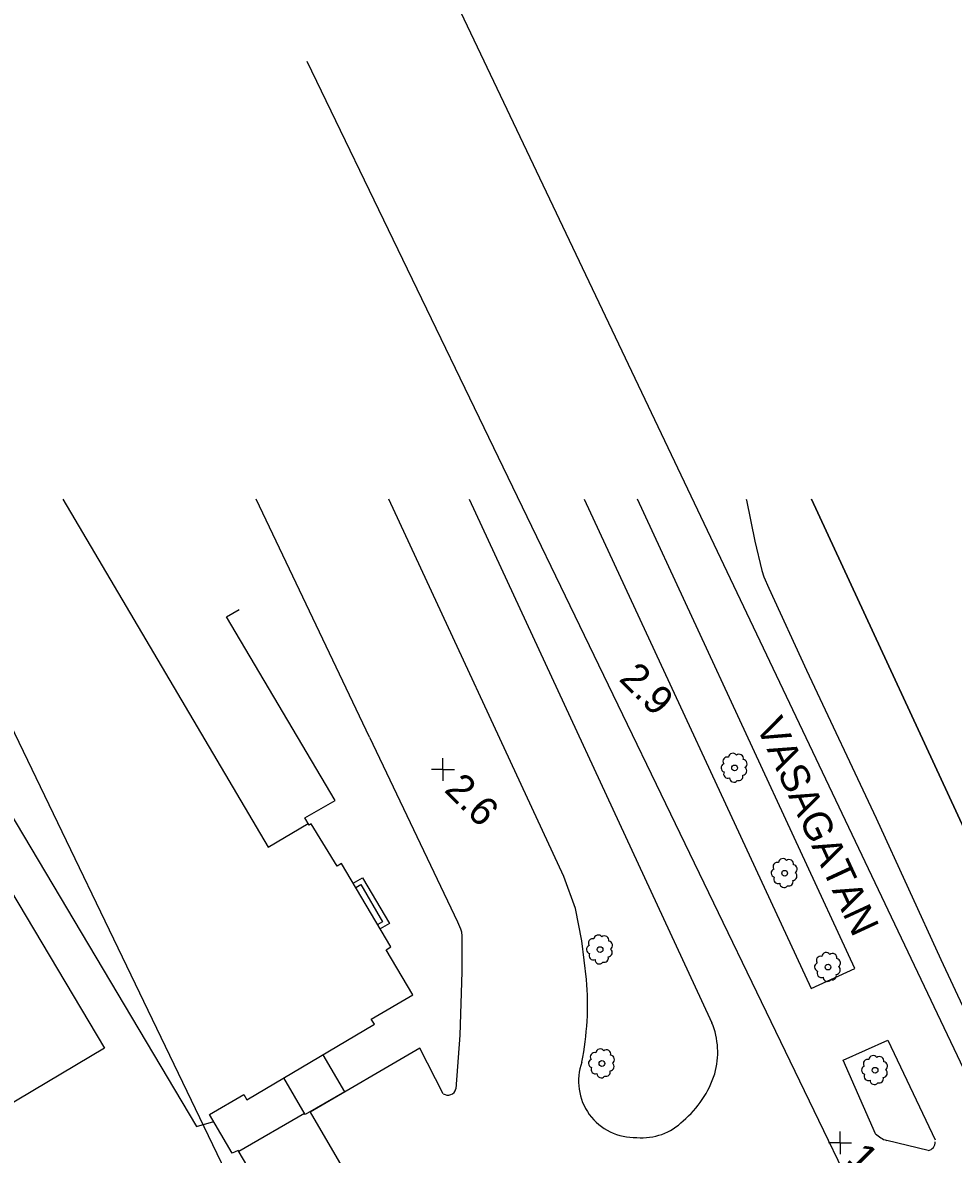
# Model space of a CAD drawing. Extents: x 1596643 to 1597288, y 13057194 to 13057957.
# Drawn here: x 1596883 to 1596964.2, y 13057602 to 13057700.7 of the extents above; entities that cross this region are included whole.
import ezdxf

# ---------------------------------------------------------------- set-up
doc = ezdxf.new("R2010")
doc.units = 0
for name, color, linetype in [('BAS byggnad anläggning L', 7, 'Continuous'), ('BAS fastighetsgräns samfällighet L', 7, 'Continuous'), ('BAS Level 16', 7, 'Continuous'), ('BAS Level 19', 7, 'Continuous'), ('BAS Level 37', 7, 'Continuous'), ('BAS lövträd P', 7, 'Continuous'), ('BAS markytetext T', 7, 'Continuous'), ('BAS trappa L', 7, 'Continuous'), ('BAS väg T', 7, 'Continuous'), ('BAS vägbanekant L', 7, 'Continuous')]:
    doc.layers.add(name, color=color, linetype=linetype)

msp = doc.modelspace()

# ---------------------------------------------------------------- linework, layer by layer
at = {"layer": 'BAS byggnad anläggning L'}
for points in [[(1596831.406, 13057716.961), (1596833.516, 13057713.232), (1596898.19, 13057604.41), (1596899.706, 13057604.86)], [(1596834.085, 13057712.226), (1596832.695, 13057711.294), (1596834.411, 13057708.471), (1596832.821, 13057707.631), (1596890.171, 13057611.249), (1596868.668, 13057598.445)], [(1596886.54, 13057659.15), (1596904.445, 13057628.802), (1596907.94, 13057630.864)], [(1596951.85, 13057659.15), (1596967.176, 13057626.043), (1596968.373, 13057623.457)], [(1596908.21, 13057630.819), (1596908.034, 13057630.704), (1596907.658, 13057631.341), (1596910.303, 13057632.867), (1596900.808, 13057648.889), (1596901.929, 13057649.518)], [(1596911.31, 13057586.299), (1596901.852, 13057602.339), (1596901.33, 13057602.091), (1596899.353, 13057605.461), (1596902.324, 13057607.201), (1596902.603, 13057606.75), (1596913.738, 13057613.344), (1596913.45, 13057613.785), (1596917.076, 13057615.913), (1596914.761, 13057619.836), (1596915.171, 13057620.084), (1596910.858, 13057627.367), (1596910.489, 13057627.128), (1596908.21, 13057630.819)], [(1596909.211, 13057610.663), (1596911.108, 13057607.434), (1596907.683, 13057605.454), (1596905.829, 13057608.661)]]:
    msp.add_lwpolyline(points, dxfattribs=at)
at = {"layer": 'BAS fastighetsgräns samfällighet L'}
for points in [[(1596920.393, 13057703.458), (1596969.695, 13057599.79)], [(1596957.924, 13057593.7), (1596907.849, 13057697.344)], [(1596913.913, 13057573.162), (1596863.532, 13057677.717)]]:
    msp.add_lwpolyline(points, dxfattribs=at)
at = {"layer": 'BAS Level 16'}
for p, q in [((1596919.698, 13057635.566), (1596919.698, 13057636.566)), ((1596919.698, 13057635.566), (1596919.698, 13057636.566)), ((1596919.698, 13057635.566), (1596918.698, 13057635.566)), ((1596919.698, 13057635.566), (1596918.698, 13057635.566)), ((1596919.698, 13057635.566), (1596920.698, 13057635.566)), ((1596919.698, 13057635.566), (1596919.698, 13057634.566)), ((1596919.698, 13057635.566), (1596920.698, 13057635.566)), ((1596919.698, 13057635.566), (1596919.698, 13057634.566)), ((1596954.343, 13057602.996), (1596954.343, 13057603.996)), ((1596954.343, 13057602.996), (1596954.343, 13057603.996)), ((1596954.343, 13057602.996), (1596953.343, 13057602.996)), ((1596954.343, 13057602.996), (1596953.343, 13057602.996)), ((1596954.343, 13057602.996), (1596955.343, 13057602.996)), ((1596954.343, 13057602.996), (1596954.343, 13057601.996)), ((1596954.343, 13057602.996), (1596955.343, 13057602.996)), ((1596954.343, 13057602.996), (1596954.343, 13057601.996))]:
    msp.add_line(p, q, dxfattribs=at)
at = {"layer": 'BAS Level 19'}
msp.add_lwpolyline([(1596907.633, 13057605.541), (1596901.893, 13057602.234)], dxfattribs=at)
at = {"layer": 'BAS Level 37'}
msp.add_lwpolyline([(1596967.176, 13057626.043), (1596951.85, 13057659.15)], dxfattribs=at)
at = {"layer": 'BAS lövträd P'}
for p, q in [((1596945.144, 13057635.703), (1596945.144, 13057635.703)), ((1596945.144, 13057635.703), (1596945.144, 13057635.703)), ((1596949.516, 13057626.517), (1596949.516, 13057626.517)), ((1596949.516, 13057626.517), (1596949.516, 13057626.517)), ((1596933.407, 13057619.852), (1596933.407, 13057619.852)), ((1596933.407, 13057619.852), (1596933.407, 13057619.852)), ((1596953.295, 13057618.326), (1596953.295, 13057618.326)), ((1596953.295, 13057618.326), (1596953.295, 13057618.326)), ((1596933.572, 13057609.914), (1596933.572, 13057609.914)), ((1596933.572, 13057609.914), (1596933.572, 13057609.914)), ((1596957.399, 13057609.329), (1596957.399, 13057609.329)), ((1596957.399, 13057609.329), (1596957.399, 13057609.329))]:
    msp.add_line(p, q, dxfattribs=at)
for centre in [(1596945.144, 13057635.703), (1596945.144, 13057635.703), (1596949.516, 13057626.517), (1596949.516, 13057626.517), (1596933.407, 13057619.852), (1596933.407, 13057619.852), (1596953.295, 13057618.326), (1596953.295, 13057618.326), (1596933.572, 13057609.914), (1596933.572, 13057609.914), (1596957.399, 13057609.329), (1596957.399, 13057609.329)]:
    msp.add_circle(centre, 0.25, dxfattribs=at)
for centre, start, end in [((1596944.34, 13057635.715), 112.50794, 253.98582), ((1596944.34, 13057635.715), 112.50794, 253.98582), ((1596944.505, 13057636.275), 73.07604, 214.55393), ((1596944.505, 13057636.275), 73.07604, 214.55393), ((1596944.988, 13057636.601), 33.64415, 175.12203), ((1596944.988, 13057636.601), 33.64415, 175.12203), ((1596945.538, 13057636.518), 347.91483, 129.39271), ((1596945.538, 13057636.518), 347.91483, 129.39271), ((1596945.858, 13057636.068), 301.35804, 82.83592), ((1596945.858, 13057636.068), 301.35804, 82.83592), ((1596944.565, 13057635.175), 151.38275, 292.86063), ((1596944.565, 13057635.175), 151.38275, 292.86063), ((1596945.498, 13057634.967), 253.13635, 15.42798), ((1596945.498, 13057634.967), 253.13635, 15.42798), ((1596945.837, 13057635.441), 273.337, 54.81488), ((1596945.837, 13057635.441), 273.337, 54.81488), ((1596945.086, 13057634.828), 179.81921, 321.29709), ((1596945.086, 13057634.828), 179.81921, 321.29709), ((1596948.877, 13057627.089), 73.07604, 214.55393), ((1596948.877, 13057627.089), 73.07604, 214.55393), ((1596949.36, 13057627.415), 33.64415, 175.12203), ((1596949.36, 13057627.415), 33.64415, 175.12203), ((1596949.91, 13057627.332), 347.91483, 129.39271), ((1596949.91, 13057627.332), 347.91483, 129.39271), ((1596950.23, 13057626.882), 301.35804, 82.83592), ((1596950.23, 13057626.882), 301.35804, 82.83592), ((1596948.712, 13057626.529), 112.50794, 253.98582), ((1596948.712, 13057626.529), 112.50794, 253.98582), ((1596948.937, 13057625.989), 151.38275, 292.86063), ((1596948.937, 13057625.989), 151.38275, 292.86063), ((1596950.209, 13057626.255), 273.337, 54.81488), ((1596950.209, 13057626.255), 273.337, 54.81488), ((1596949.458, 13057625.642), 179.81921, 321.29709), ((1596949.458, 13057625.642), 179.81921, 321.29709), ((1596949.87, 13057625.781), 253.13635, 15.42798), ((1596949.87, 13057625.781), 253.13635, 15.42798), ((1596932.603, 13057619.864), 112.50794, 253.98582), ((1596932.603, 13057619.864), 112.50794, 253.98582), ((1596932.768, 13057620.424), 73.07604, 214.55393), ((1596932.768, 13057620.424), 73.07604, 214.55393), ((1596933.251, 13057620.75), 33.64415, 175.12203), ((1596933.251, 13057620.75), 33.64415, 175.12203), ((1596933.801, 13057620.667), 347.91483, 129.39271), ((1596933.801, 13057620.667), 347.91483, 129.39271), ((1596934.121, 13057620.217), 301.35804, 82.83592), ((1596934.121, 13057620.217), 301.35804, 82.83592), ((1596932.828, 13057619.324), 151.38275, 292.86063), ((1596932.828, 13057619.324), 151.38275, 292.86063), ((1596934.1, 13057619.59), 273.337, 54.81488), ((1596934.1, 13057619.59), 273.337, 54.81488), ((1596952.656, 13057618.898), 73.07604, 214.55393), ((1596952.656, 13057618.898), 73.07604, 214.55393), ((1596953.139, 13057619.224), 33.64415, 175.12203), ((1596953.139, 13057619.224), 33.64415, 175.12203), ((1596953.689, 13057619.141), 347.91483, 129.39271), ((1596953.689, 13057619.141), 347.91483, 129.39271), ((1596933.349, 13057618.977), 179.81921, 321.29709), ((1596933.349, 13057618.977), 179.81921, 321.29709), ((1596933.761, 13057619.116), 253.13635, 15.42798), ((1596933.761, 13057619.116), 253.13635, 15.42798), ((1596952.491, 13057618.338), 112.50794, 253.98582), ((1596952.491, 13057618.338), 112.50794, 253.98582), ((1596953.988, 13057618.064), 273.337, 54.81488), ((1596953.988, 13057618.064), 273.337, 54.81488), ((1596954.009, 13057618.691), 301.35804, 82.83592), ((1596954.009, 13057618.691), 301.35804, 82.83592), ((1596952.716, 13057617.798), 151.38275, 292.86063), ((1596952.716, 13057617.798), 151.38275, 292.86063), ((1596953.237, 13057617.451), 179.81921, 321.29709), ((1596953.237, 13057617.451), 179.81921, 321.29709), ((1596953.649, 13057617.59), 253.13635, 15.42798), ((1596953.649, 13057617.59), 253.13635, 15.42798), ((1596932.933, 13057610.486), 73.07604, 214.55393), ((1596932.933, 13057610.486), 73.07604, 214.55393), ((1596933.416, 13057610.812), 33.64415, 175.12203), ((1596933.416, 13057610.812), 33.64415, 175.12203), ((1596933.966, 13057610.729), 347.91483, 129.39271), ((1596933.966, 13057610.729), 347.91483, 129.39271), ((1596934.286, 13057610.279), 301.35804, 82.83592), ((1596934.286, 13057610.279), 301.35804, 82.83592), ((1596957.243, 13057610.227), 33.64415, 175.12203), ((1596957.243, 13057610.227), 33.64415, 175.12203), ((1596957.793, 13057610.144), 347.91483, 129.39271), ((1596957.793, 13057610.144), 347.91483, 129.39271), ((1596932.768, 13057609.926), 112.50794, 253.98582), ((1596932.768, 13057609.926), 112.50794, 253.98582), ((1596932.993, 13057609.386), 151.38275, 292.86063), ((1596932.993, 13057609.386), 151.38275, 292.86063), ((1596934.265, 13057609.652), 273.337, 54.81488), ((1596934.265, 13057609.652), 273.337, 54.81488), ((1596956.595, 13057609.341), 112.50794, 253.98582), ((1596956.595, 13057609.341), 112.50794, 253.98582), ((1596956.76, 13057609.901), 73.07604, 214.55393), ((1596956.76, 13057609.901), 73.07604, 214.55393), ((1596958.092, 13057609.067), 273.337, 54.81488), ((1596958.092, 13057609.067), 273.337, 54.81488), ((1596958.113, 13057609.694), 301.35804, 82.83592), ((1596958.113, 13057609.694), 301.35804, 82.83592), ((1596933.514, 13057609.039), 179.81921, 321.29709), ((1596933.514, 13057609.039), 179.81921, 321.29709), ((1596933.926, 13057609.178), 253.13635, 15.42798), ((1596933.926, 13057609.178), 253.13635, 15.42798), ((1596956.82, 13057608.801), 151.38275, 292.86063), ((1596956.82, 13057608.801), 151.38275, 292.86063), ((1596957.341, 13057608.454), 179.81921, 321.29709), ((1596957.341, 13057608.454), 179.81921, 321.29709), ((1596957.753, 13057608.593), 253.13635, 15.42798), ((1596957.753, 13057608.593), 253.13635, 15.42798)]:
    msp.add_arc(centre, 0.375, start, end, dxfattribs=at)
at = {"layer": 'BAS trappa L'}
for points in [[(1596911.883, 13057625.657), (1596912.688, 13057626.107), (1596915.031, 13057622.119), (1596914.224, 13057621.664)], [(1596912.093, 13057625.282), (1596912.531, 13057625.526), (1596914.438, 13057622.279), (1596914.013, 13057622.04)]]:
    msp.add_lwpolyline(points, dxfattribs=at)
at = {"layer": 'BAS vägbanekant L'}
for points in [[(1596913.294, 13057638.378), (1596903.4, 13057659.15)], [(1596932.238, 13057617.243), (1596931.82, 13057620.62), (1596931.277, 13057623.444), (1596930.256, 13057626.24), (1596914.975, 13057659.15)], [(1596921.994, 13057659.15), (1596942.273, 13057615.424)], [(1596932.036, 13057659.15), (1596951.816, 13057616.456), (1596955.621, 13057618.209), (1596936.662, 13057659.15)], [(1596946.154, 13057659.15), (1596946.174, 13057659.066), (1596946.919, 13057655.489), (1596947.514, 13057652.919), (1596947.689, 13057652.358), (1596948.144, 13057651.387), (1596951.431, 13057644.239), (1596957.487, 13057631.323), (1596963.144, 13057618.982), (1596968.373, 13057607.797)], [(1596913.294, 13057638.378), (1596920.983, 13057622.285), (1596921.229, 13057621.672), (1596921.327, 13057621.396), (1596921.342, 13057621.01), (1596921.351, 13057617.92), (1596921.175, 13057612.383), (1596920.837, 13057607.692)], [(1596942.273, 13057615.424), (1596943.17, 13057613.475)], [(1596957.451, 13057603.79), (1596954.621, 13057610.209), (1596958.516, 13057611.958), (1596962.657, 13057603.254)], [(1596919.734, 13057607.279), (1596917.673, 13057611.25), (1596908.106, 13057605.662), (1596910.878, 13057600.93)], [(1596962.025, 13057602.317), (1596958.419, 13057603.208)]]:
    msp.add_lwpolyline(points, dxfattribs=at)
for centre, radius, start, end in [((1596905.53, 13057615.135), 26.791, 349.01092, 4.51287), ((1596936.822, 13057610.897), 6.851, 344.13644, 22.10586), ((1596936.43, 13057608.354), 4.895, 160.00629, 272.13682), ((1596934.954, 13057611.727), 8.88, 309.9978, 342.27505), ((1596920.14, 13057607.874), 0.72, 235.69221, 345.36574), ((1596937.106, 13057608.433), 4.995, 264.33751, 315.38947), ((1596958.896, 13057605.099), 1.95, 222.19465, 255.84262), ((1596961.908, 13057603.046), 0.738, 279.11786, 3.57149)]:
    msp.add_arc(centre, radius, start, end, dxfattribs=at)

# ---------------------------------------------------------------- texts
at = {"layer": 'BAS markytetext T'}
for s, p in [('2.9', (1596934.975, 13057643.378)), ('2.6', (1596919.724, 13057633.707)), ('1.9', (1596954.807, 13057601.472))]:
    msp.add_text(s, height=2.5, rotation=315, dxfattribs=at).set_placement(p)
at = {"layer": 'BAS väg T'}
msp.add_text('VASAGATAN', height=2.5, rotation=294.813, dxfattribs=at).set_placement((1596946.98, 13057639.38))

doc.saveas('drawing.dxf')
